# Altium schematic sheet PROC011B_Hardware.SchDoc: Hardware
size 431 x 279 mm; Date: Not shown in title block; ApprovedBy: Not shown in title block; CheckedBy: Not shown in title block; Author: Not shown in title block; CompanyName: Not shown in title block; Engineer: Not shown in title block; Organization: Not shown in title block; Address1: Not shown in title block; Address2: Not shown in title block; Address3: Not shown in title block; Address4: Not shown in title block; DocumentNumber: 1; Revision: Use project parameter SCH_Rev; SheetNumber: 17; SheetTotal: 17; PageSetup: Record=PageOptions¦CenterHorizontal=True¦CenterVertical=True¦PrintScale=1.00¦XCorrection=1.00¦YCorrection=1.00¦PrintKind=0¦BorderSize=5000000¦LeftOffset=0¦BottomOffset=0¦Orientation=2¦PaperLength=1000¦PaperWidth=1000¦Scale=100¦PaperSource=15¦PrintQuality=600¦MediaType=1¦DitherType=10¦PaperKind=Letter¦PrintScaleMode=1
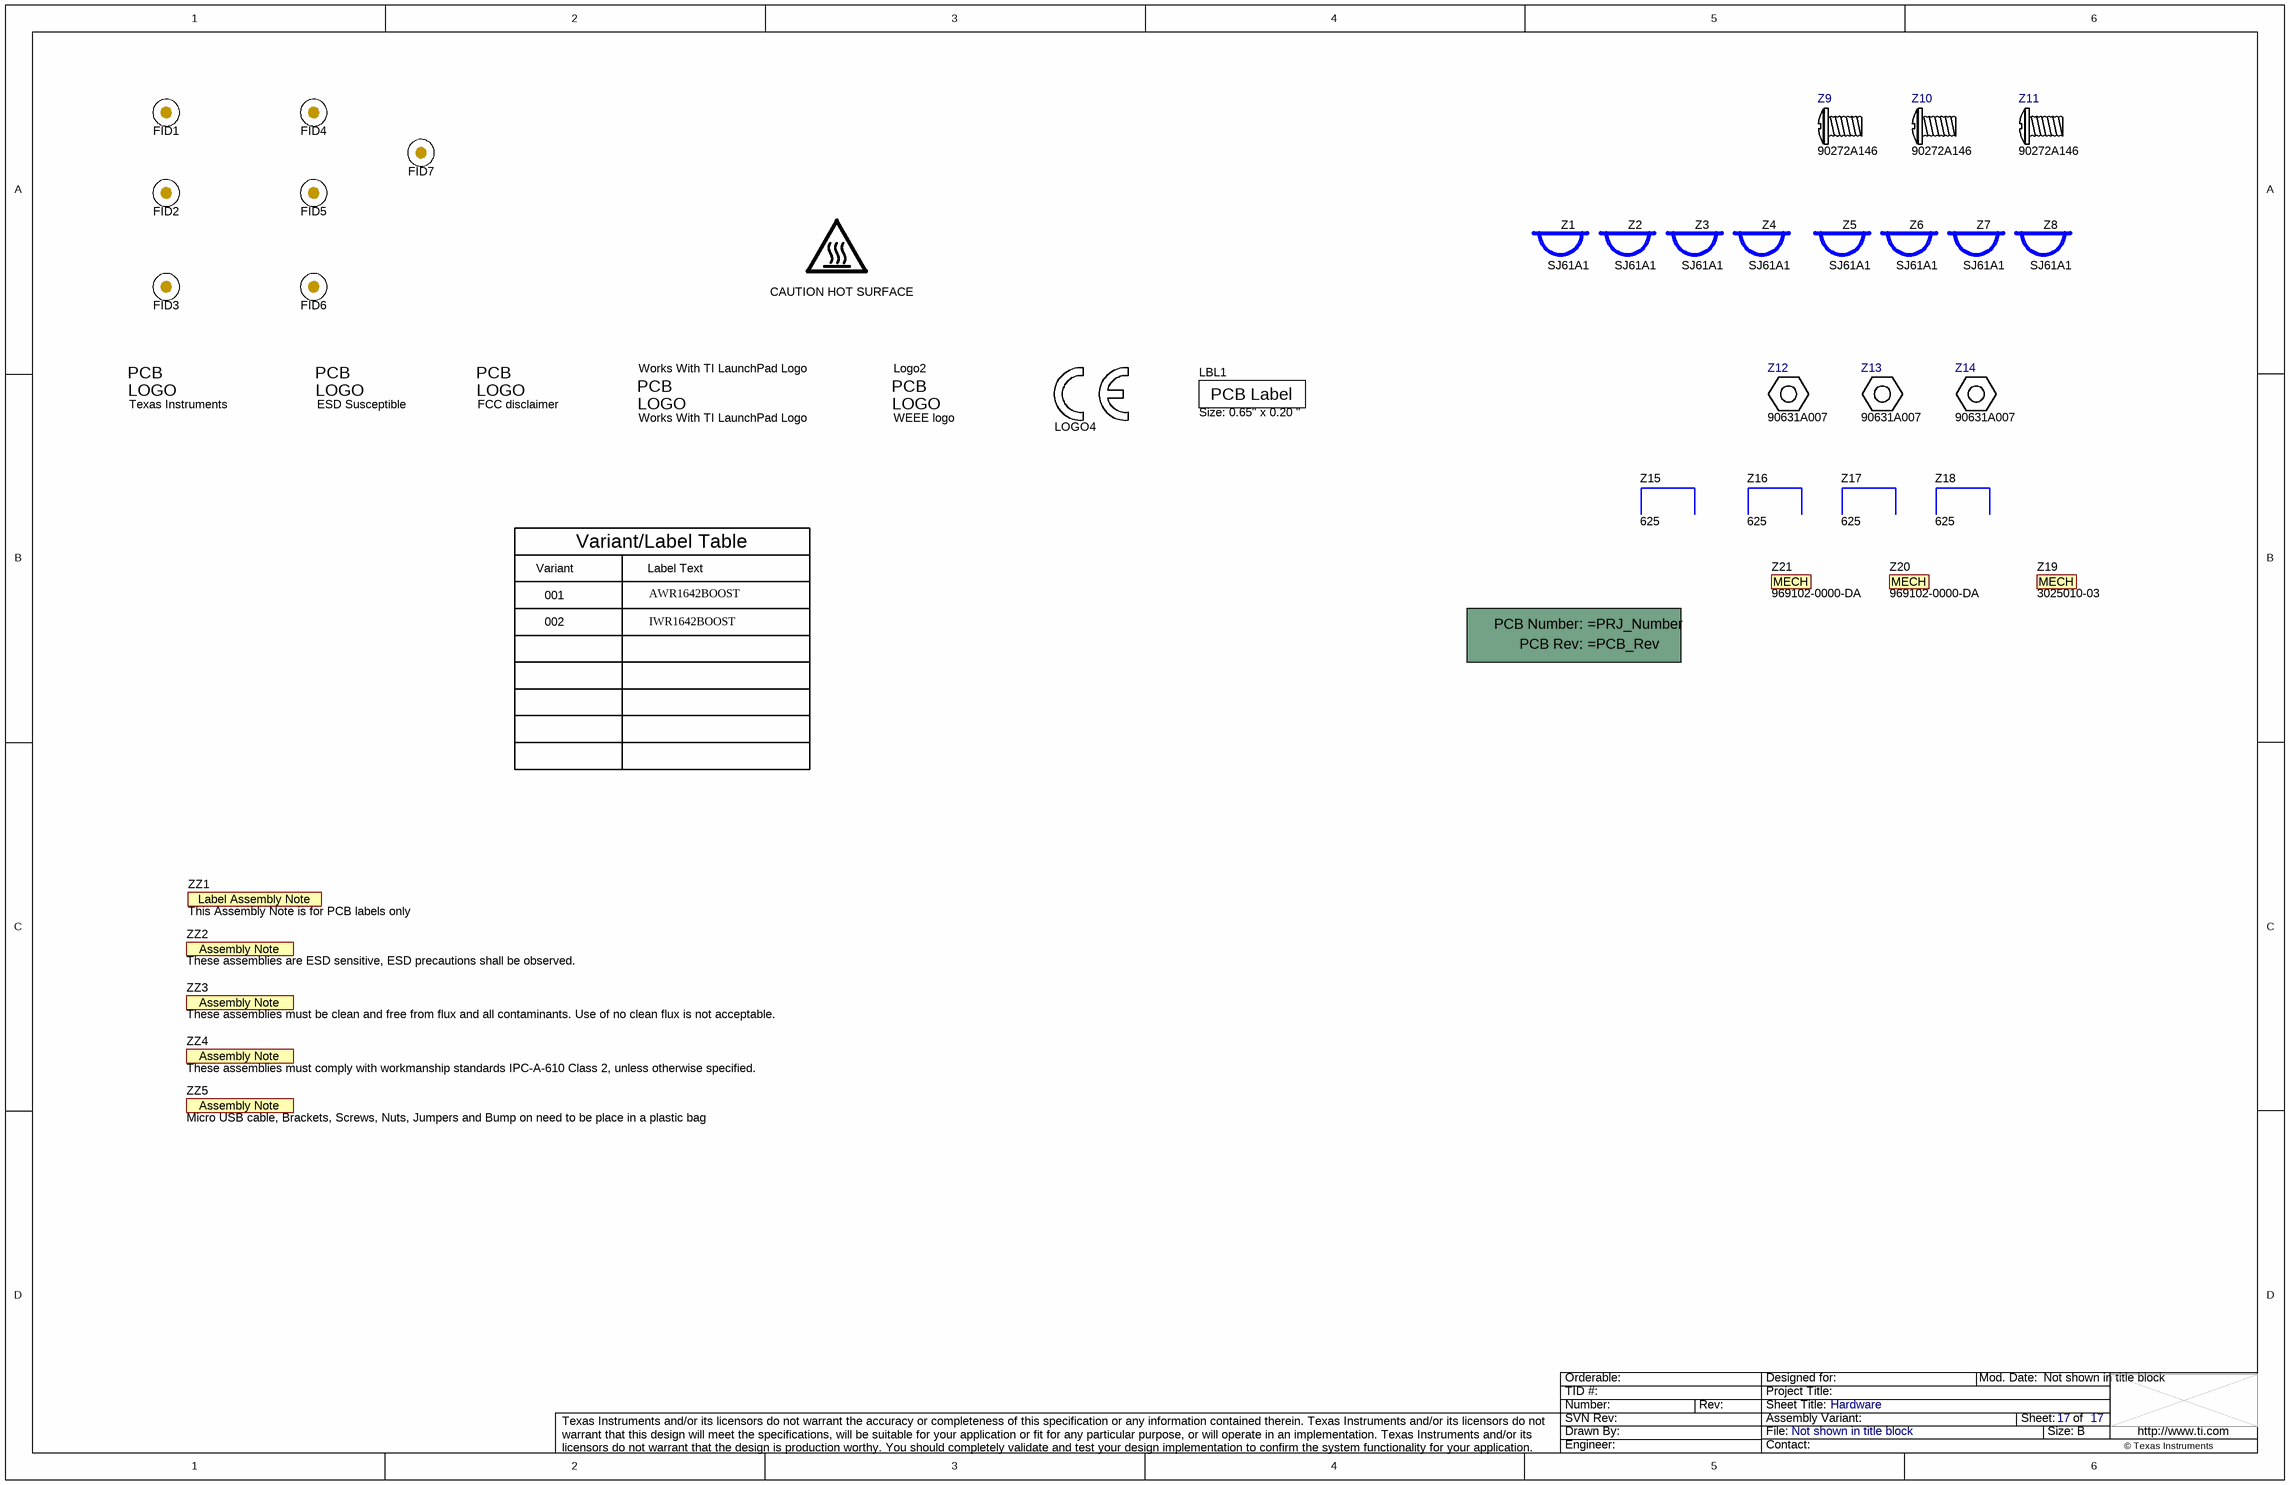
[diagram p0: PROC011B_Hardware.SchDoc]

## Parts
!PCB  PROC011  (value not drawn)  (mechanical)
CAUTION_HOT_SURFACE  CAUTION HOT SURFACE  [IEC_HotSurface_Small]  (no BOM)
ESD_Susceptible  ESD Susceptible  [ESD_Overlay_Small]  (no BOM)
FID1  Fiducial  [Fiducial10-20]  (value not drawn)
FID2  Fiducial  [Fiducial10-20]  (value not drawn)
FID3  Fiducial  [Fiducial10-20]  (value not drawn)
FID4  Fiducial  [Fiducial10-20]  (value not drawn)
FID5  Fiducial  [Fiducial10-20]  (value not drawn)
FID6  Fiducial  [Fiducial10-20]  (value not drawn)
FID7  Fiducial  [Fiducial10-20]  (value not drawn)
LBL1  Size: 0.65" x 0.20 "  [Label_650x200]
Logo1  Texas Instruments  [TI_Stacked_Overlay_Small]  (no BOM)
Logo2  WEEE logo  [WEEE_Minimum]  (no BOM)
Logo3  FCC disclaimer  [FCC_disclaimer]  (no BOM)
LOGO4  CE Mark  [CE_Mark_5mm]  (value not drawn)  (no BOM)
Works_With_TI_LaunchPad_Logo  Works With TI LaunchPad Logo  [WorksWithTILaunchPad]  (mechanical)
Z1  SJ61A1  (mechanical)
Z2  SJ61A1  (mechanical)
Z3  SJ61A1  (mechanical)
Z4  SJ61A1  (mechanical)
Z5  SJ61A1  (mechanical)
Z6  SJ61A1  (mechanical)
Z7  SJ61A1  (mechanical)
Z8  SJ61A1  (mechanical)
Z9  90272A146  (mechanical)
Z10  90272A146  (mechanical)
Z11  90272A146  (mechanical)
Z12  90631A007  (mechanical)
Z13  90631A007  (mechanical)
Z14  90631A007  (mechanical)
Z15  625  (mechanical)
Z16  625  (mechanical)
Z17  625  (mechanical)
Z18  625  (mechanical)
Z19  3025010-03  (mechanical)
Z20  969102-0000-DA  (mechanical)
Z21  969102-0000-DA  (mechanical)
ZZ1  This Assembly Note is for PCB labels only  [AssemblyNoteLabel]  (no BOM)
ZZ2  These assemblies are ESD sensitive, ESD precautions shall be observed.  [AssemblyNote]  (no BOM)
ZZ3  These assemblies must be clean and free from flux and all contaminants. Use of no clean flux is not acceptable.  [AssemblyNote]  (no BOM)
ZZ4  These assemblies must comply with workmanship standards IPC-A-610 Class 2, unless otherwise specified.  [AssemblyNote]  (no BOM)
ZZ5  Micro USB cable, Brackets, Screws, Nuts, Jumpers and Bump on need to be place in a plastic bag  [AssemblyNote]  (no BOM)

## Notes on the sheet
- Variant
- Variant/Label Table
- Label Text
- 001
- 002
- AWR1642BOOST
- IWR1642BOOST

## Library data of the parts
!PCB = CMP-0003618-2: Printed Circuit Board; Manufacturer: Any; CompType: PCB
CAUTION_HOT_SURFACE = CMP-0074837-1: IEC 61010-1 Hot Surface Warning; Library Reference: IEC_HotSurface; SymbolCreator: a0412235
ESD_Susceptible = CMP-0074840-1: ESD Susceptible Symbol; Library Reference: Logo; SymbolCreator: a0412235; Lib Reference: ESD_Susceptible
FID1-FID7 = CMP-0077181-1: Fiducial mark.  There is nothing to buy or mount.
LBL1 = THT-14-423-10: Thermal Transfer Printable Labels, 0.650" W x 0.200" H - 10,000 per roll; Manufacturer: Brady; SymbolCreator: a0412235; CompType: Label
Logo1 = CMP-0074838-1: Texas Instrument Corporate Signature; SymbolCreator: a0412235; Lib Reference: TI_Logo; Library Reference: Logo
Logo2 = CMP-0074769-1
Logo3 = CMP-0074847-1: FCC_disclaimer; Library Reference: Logo
LOGO4 = CE Mark: SymbolCreator: a0412235
Works_With_TI_LaunchPad_Logo = CMP-0077108-1
Z1-Z8 = SJ61A1: Bumpon, Cylindrical, 0.312 X 0.200, Black; Manufacturer: 3M; SymbolCreator: a0412235; Green_Lifecycle: Not Set; Green_REACh: Incomplete
Z9-Z11 = NY PMS 256 0050 PH: Screw, Pan Philips, Nylon, 2-56; Manufacturer: B&F Fastener Supply; SymbolCreator: a0412235
Z12-Z14 = HNSS 832: Nut, Hex, 11/32" Stainless Steel, 8-32; Manufacturer: mcmaster
Z15-Z18 = PCC-SMP-CLIP: BRACKET MOUNTIG ALUM; Manufacturer: Keystone Electronics; CompType: Hardware
Z19 = AK672M/2-1-R: CABLE MINI USB 5PIN 1M 2.0 VERS; CompType: CABLE USB
Z20 Z21 = 0050579402: 2 (1 x 2) Position Shunt Connector Black Open Top 0.100" (2.54mm) Gold
ZZ1 = AssemblyNoteLabel: SymbolCreator: a0412235
ZZ2-ZZ5 = AssemblyNote: SymbolCreator: codlsc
